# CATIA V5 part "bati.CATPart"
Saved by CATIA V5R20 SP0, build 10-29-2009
Part number: bati
Bounding box of the stored display mesh (mm): x -20 to 20, y -20 to 240, z 0 to 225
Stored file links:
  C:\Users\Willy\Documents\ThinkMotion\646\bati.CATPart
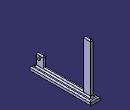
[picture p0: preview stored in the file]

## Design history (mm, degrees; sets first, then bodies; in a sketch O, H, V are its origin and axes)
Body1 (main body)
  Sketch1 on xy-plane, origin (0, 0, 0), H (1, 0, 0), V (0, 1, 0)
    line L1 (-20, 240) -> (20, 240)
    line L2 (20, 240) -> (20, -20)
    line L3 (20, -20) -> (-20, -20)
    line L4 (-20, -20) -> (-20, 240)
    length L3 = 40
    length L2 = 260
    horizontal: L1 H, L3 H
    vertical: L2 V, L4 V
  Pad1: profile Sketch1, direction (0, 0, 1), length 15
  Sketch2 on face of Pad1 from Sketch1.L2, origin (20, 0, 0), H (0, 1, 0), V (0, 0, 1)
    circle A1 centre (7.3695, 51.1169) radius 5
    point P1 (7.3695, 51.1169)
    circle A2 centre (209.2613, 214.9451) radius 5
    point P2 (209.2613, 214.9451)
    line L1 (-7.6305, 15) -> (-7.6305, 65)
    line L2 (-7.6305, 65) -> (22.3695, 65)
    line L3 (22.3695, 65) -> (22.3695, 25)
    line L4 (22.3695, 25) -> (194.2613, 25)
    line L5 (194.2613, 25) -> (194.2613, 225)
    line L6 (194.2613, 225) -> (224.2613, 225)
    line L7 (224.2613, 225) -> (224.2613, 15)
    line L8 (224.2613, 15) -> (-7.6305, 15)
    reference projected line E1 (-20, 15) -> (240, 15) from edge [face of Pad1 from Sketch1.L2 | end face of Pad1]
    radius A2 = 5
    radius A1 = 5
    distance P1 P2 = 260
    distance L5 L7 = 30
    length L2 = 30
    vertical: L1 V, L3 V, L5 V, L7 V
    horizontal: L2 H, L4 H, L6 H, L8 H
    coincidence: L8 E1
    equidistance: L5 L7 P2, L1 L3 P1
  Pad2: profile Sketch2, direction (-1, 0, 0), length 25, opposite side length -15
  Fillet1: radius 5, on end face of Pad1; face of Pad2 from Sketch2.L2; face of Pad2 from Sketch2.L4; face of Pad2 from Sketch2.L6
  Sketch3 on start face of Pad2, origin (5, 0, 0), H (0, 1, 0), V (0, 0, 1)
    circle A1 centre (209.2613, 214.9451) radius 5
    reference projected circle E1 centre (209.2613, 214.9451) radius 5 from edge [start face of Pad2 | face of Pad2 from Sketch2.A2]
    coincidence: E1 A1
  Pad3: profile Sketch3, direction (-1, 0, 0), length 15
  Sketch4 on end face of Pad2, origin (-5, 0, 0), H (0, -1, 0), V (0, 0, 1)
    circle A1 centre (-7.3695, 51.1169) radius 5
    reference projected circle E1 centre (-7.3695, 51.1169) radius 5 from edge [face of Pad2 from Sketch2.A1 | end face of Pad2]
    coincidence: E1 A1
  Pad4: profile Sketch4, direction (1, 0, 0), length 15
